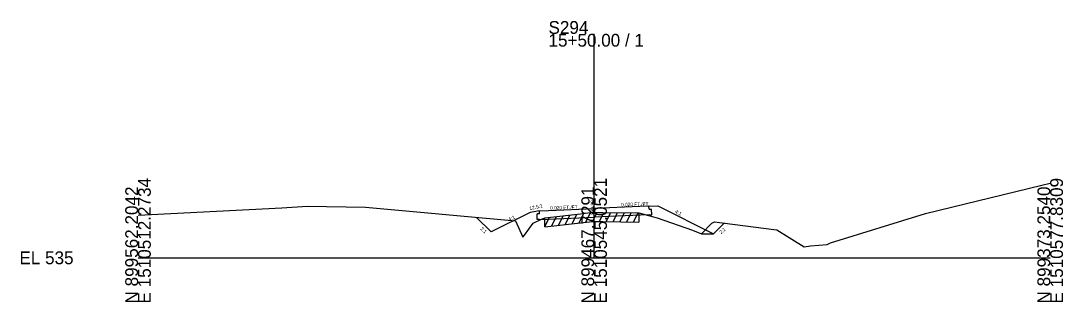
# Model space of a CAD drawing. Extents: x 974 to 2203, y -10 to 19041.
# Drawn here: x 974.3 to 1202.8, y 10990.3 to 11051.8 of the extents above; entities that cross this region are included whole.
import ezdxf

# ---------------------------------------------------------------- set-up
doc = ezdxf.new("R2010")
doc.units = 0
for name, color, linetype in [('RD_EX_TX_H2O_WetLd_ELEV', 7, 'Continuous'), ('RD_GPK_XS_Cell', 7, 'Continuous'), ('RD_XS_Base', 7, 'Continuous'), ('RD_XS_EarthShd', 7, 'Continuous'), ('RD_XS_ExGround', 7, 'Continuous'), ('RD_XS_ExPaveRet', 7, 'Continuous'), ('RD_XS_Pave', 7, 'Continuous'), ('RD_XS_TX_Elev_EX', 7, 'Continuous'), ('RD_XS_TX_Slope', 7, 'Continuous')]:
    doc.layers.add(name, color=color, linetype=linetype)

msp = doc.modelspace()

# ---------------------------------------------------------------- linework, layer by layer
at = {"layer": 'RD_EX_TX_H2O_WetLd_ELEV'}
msp.add_line((1123.58, 11005.26), (1126.21, 11005.25), dxfattribs=at)
at = {"layer": 'RD_GPK_XS_Cell'}
for p, q in [((1100, 11000), (1100, 11049.01)), ((1000, 11000), (1100, 11000)), ((1100, 11000), (1200, 11000))]:
    msp.add_line(p, q, dxfattribs=at)
at = {"layer": 'RD_XS_Base'}
for p, q in [((1112.05, 11010.65), (1112, 11011.28)), ((1088, 11009.64), (1087.5, 11009.62)), ((1087.5, 11008.35), (1087.5, 11009.62)), ((1088, 11009.64), (1088, 11010.28)), ((1088, 11008.37), (1090, 11008.46)), ((1090, 11008.46), (1099.99, 11008.87)), ((1110.16, 11009.3), (1099.99, 11008.87)), ((1112.16, 11009.38), (1110.16, 11009.3)), ((1112.05, 11010.65), (1112.55, 11010.67)), ((1112.16, 11009.38), (1112.66, 11009.4)), ((1112.66, 11009.4), (1112.55, 11010.67)), ((1088, 11008.37), (1087.5, 11008.35))]:
    msp.add_line(p, q, dxfattribs=at)
at = {"layer": 'RD_XS_EarthShd'}
for p, q in [((1112, 11011.28), (1114, 11011.36)), ((1114, 11011.36), (1126.21, 11005.25)), ((1077.4, 11005.65), (1074.21, 11008.84)), ((1086, 11009.95), (1077.4, 11005.65)), ((1088, 11010.28), (1086, 11009.95)), ((1126.21, 11005.25), (1128.59, 11007.63))]:
    msp.add_line(p, q, dxfattribs=at)
at = {"layer": 'RD_XS_ExGround'}
msp.add_lwpolyline([(1000, 11009.37), (1031.52, 11010.97), (1037.07, 11011.32), (1049.88, 11011.06), (1082.73, 11008.06), (1084.37, 11004.54), (1084.74, 11004.99), (1086.66, 11007.55), (1088.5, 11008.46), (1089.17, 11008.76), (1097.02, 11009.64), (1099.63, 11009.97), (1100, 11009.96), (1101.93, 11009.93), (1109.82, 11009.83), (1112.74, 11009.01), (1113.8, 11008.75), (1121.58, 11006.02), (1123.58, 11005.26), (1125.83, 11007.57), (1126.43, 11007.9), (1139.4, 11006.23), (1140.09, 11006.15), (1146.07, 11002.43), (1147.41, 11002.62), (1151.12, 11002.91), (1151.83, 11003.29), (1172.66, 11009.73), (1198.15, 11015.89), (1200, 11016.34)], dxfattribs=at)
at = {"layer": 'RD_XS_ExPaveRet'}
for p, q in [((1089.17, 11006.76), (1090.23, 11008.88)), ((1089.17, 11006.76), (1089.17, 11008.76)), ((1090.67, 11006.93), (1091.73, 11009.05)), ((1092.17, 11007.1), (1093.23, 11009.22)), ((1093.67, 11007.27), (1094.73, 11009.39)), ((1095.17, 11007.43), (1096.23, 11009.55)), ((1096.67, 11007.6), (1097.74, 11009.73)), ((1098.17, 11007.79), (1099.24, 11009.92)), ((1099.67, 11007.97), (1100.66, 11009.95)), ((1101.17, 11007.94), (1102.16, 11009.93)), ((1102.67, 11007.92), (1103.66, 11009.91)), ((1104.17, 11007.9), (1105.16, 11009.89)), ((1105.67, 11007.88), (1106.66, 11009.87)), ((1107.17, 11007.86), (1108.16, 11009.85)), ((1108.67, 11007.84), (1109.66, 11009.83)), ((1109.82, 11009.83), (1109.82, 11007.83)), ((1089.17, 11006.76), (1097.02, 11007.64)), ((1097.02, 11007.64), (1099.63, 11007.97)), ((1099.63, 11007.97), (1100, 11007.96)), ((1100, 11007.96), (1101.93, 11007.93)), ((1101.93, 11007.93), (1109.82, 11007.83))]:
    msp.add_line(p, q, dxfattribs=at)
at = {"layer": 'RD_XS_Pave'}
for p, q in [((1090, 11010.36), (1100, 11010.78)), ((1110, 11011.2), (1100, 11010.78)), ((1112, 11011.28), (1110, 11011.2)), ((1088, 11010.28), (1090, 11010.36))]:
    msp.add_line(p, q, dxfattribs=at)

# ---------------------------------------------------------------- texts
at = {"layer": 'RD_GPK_XS_Cell'}
for s, p in [('S294', (1090, 11049.01)), ('15+50.00 / 1', (1090, 11046.21)), ('EL 535', (974, 10998.6))]:
    msp.add_text(s, height=2.8, dxfattribs=at).set_placement(p)
for s, p in [('N 899562.2042', (1000, 10990)), ('E 1510512.2734', (1002.8, 10990)), ('N 899467.7291', (1100, 10990)), ('E 1510545.0521', (1102.8, 10990)), ('N 899373.2540', (1200, 10990)), ('E 1510577.8309', (1202.8, 10990))]:
    msp.add_text(s, height=2.8, rotation=90, dxfattribs=at).set_placement(p)
at = {"layer": 'RD_XS_TX_Elev_EX'}
msp.add_text('539.98', height=0.75, rotation=90, dxfattribs=at).set_placement((1100, 11009.43))
at = {"layer": 'RD_XS_TX_Slope'}
for s, height, rotation, p in [('12.5:1', 0.778, 12.7511, (1085.88, 11010.41)), ('0.020 FT./FT.', 0.7518, 1.8449, (1090.38, 11010.54)), ('0.020 FT./FT.', 0.7518, 2.1396, (1105.93, 11011.24)), ('4:1', 0.778, 26.3688, (1081.44, 11007.98)), ('4:1', 0.778, 333.6312, (1117.62, 11009.87)), ('2:1', 0.778, 319.3411, (1074.94, 11006.26)), ('2:1', 0.778, 40.6589, (1127.82, 11005.14))]:
    msp.add_text(s, height=height, rotation=rotation, dxfattribs=at).set_placement(p)

doc.saveas('drawing.dxf')
